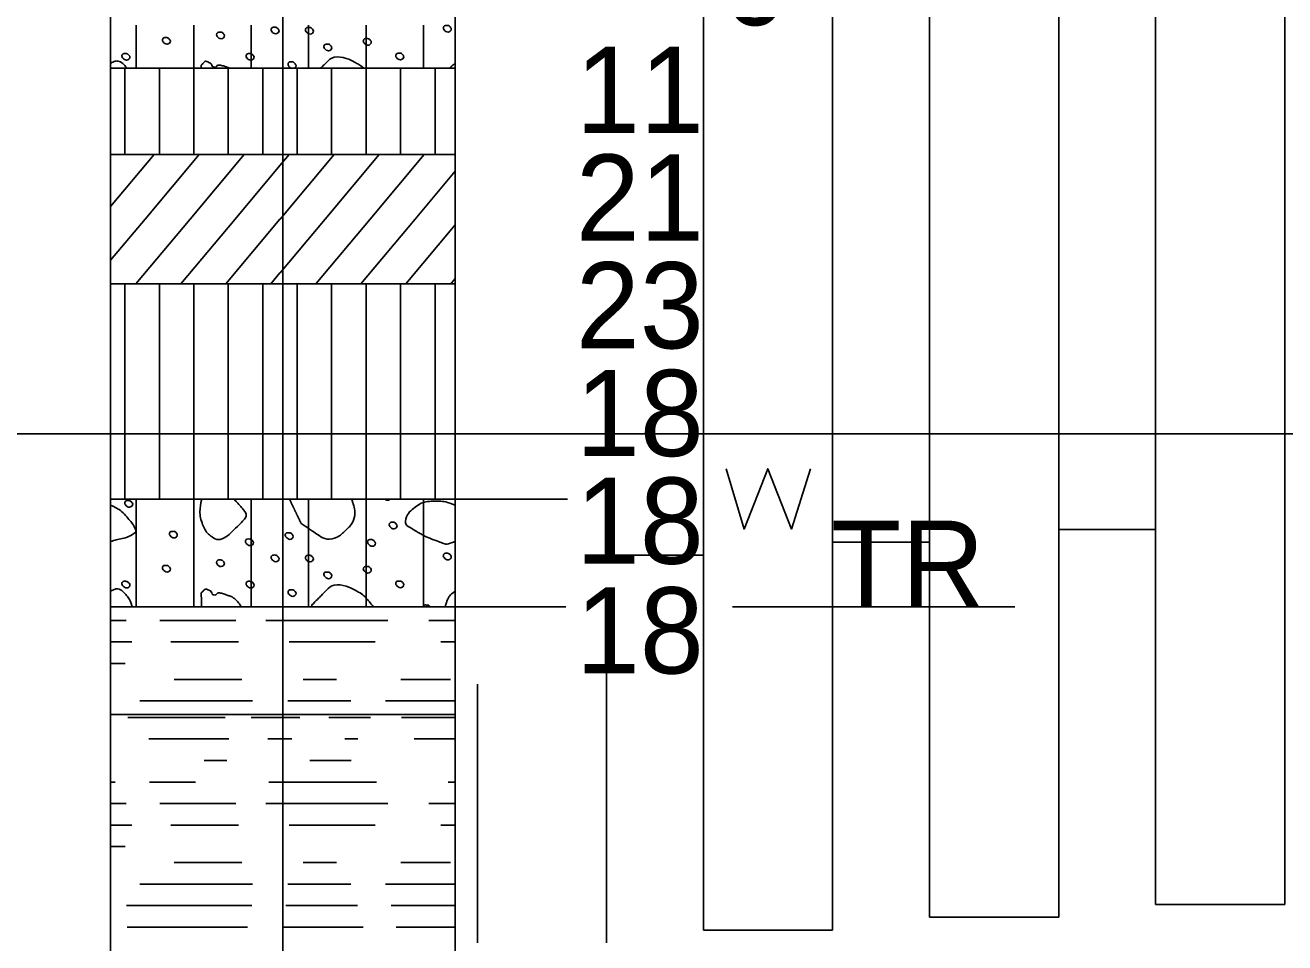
# Model space of a CAD drawing. Extents: x -2280229 to 1306, y -58886 to 440.
# Drawn here: x 316.23 to 345.48, y 70.4 to 91.69 of the extents above; entities that cross this region are included whole.
import ezdxf

# ---------------------------------------------------------------- set-up
doc = ezdxf.new("R2010")
doc.units = 0
for name, color, linetype in [('BR_P_Sub_Deep_Object', 7, 'Continuous'), ('GT_Project_Cells', 7, 'Continuous'), ('GT_Project_Soil_Layers', 7, 'Continuous'), ('SC_Scratch2', 7, 'Continuous'), ('SC_Scratch3', 7, 'Continuous'), ('SH_Minor_Grid_Line', 7, 'Continuous')]:
    doc.layers.add(name, color=color, linetype=linetype)

msp = doc.modelspace()

# ---------------------------------------------------------------- linework, layer by layer
at = {"layer": 'BR_P_Sub_Deep_Object'}
for p, q in [((331.984, 106.857), (331.984, 70.692)), ((334.984, 106.85), (334.984, 70.692)), ((337.234, 106.845), (337.234, 70.988)), ((340.234, 106.839), (340.234, 70.988)), ((342.484, 106.833), (342.484, 71.283)), ((345.484, 106.847), (345.484, 71.283)), ((340.234, 79.988), (342.484, 79.988)), ((334.984, 79.692), (337.234, 79.692)), ((329.734, 79.396), (331.984, 79.396)), ((329.734, 76.788), (329.734, 70.396)), ((326.734, 76.396), (326.734, 70.396)), ((342.484, 71.283), (345.484, 71.283)), ((337.234, 70.988), (340.234, 70.988)), ((331.984, 70.692), (334.984, 70.692))]:
    msp.add_line(p, q, dxfattribs=at)
at = {"layer": 'GT_Project_Cells'}
msp.add_line((328.828, 80.693), (326.219, 80.693), dxfattribs=at)
msp.add_lwpolyline([(332.509, 81.4), (332.927, 80), (333.479, 81.4), (334.03, 80), (334.471, 81.4)], dxfattribs=at)
at = {"layer": 'GT_Project_Soil_Layers'}
for p, q in [((318.815, 90.693), (318.815, 91.692)), ((320.148, 90.693), (320.148, 91.692)), ((321.481, 90.693), (321.481, 91.692)), ((322.817, 90.693), (322.817, 91.692)), ((324.151, 90.693), (324.151, 91.692)), ((325.484, 90.693), (325.484, 91.692)), ((318.551, 89.693), (318.551, 90.693)), ((319.351, 89.693), (319.351, 90.693)), ((320.151, 89.693), (320.151, 90.693)), ((320.951, 89.693), (320.951, 90.693)), ((321.751, 89.693), (321.751, 90.693)), ((322.551, 89.693), (322.551, 90.693)), ((323.351, 89.693), (323.351, 90.693)), ((324.151, 89.693), (324.151, 90.693)), ((324.951, 89.693), (324.951, 90.693)), ((325.751, 89.693), (325.751, 90.693)), ((318.551, 88.693), (318.551, 89.693)), ((319.351, 88.693), (319.351, 89.693)), ((320.151, 88.693), (320.151, 89.693)), ((320.951, 88.693), (320.951, 89.693)), ((321.751, 88.693), (321.751, 89.693)), ((322.551, 88.693), (322.551, 89.693)), ((323.351, 88.693), (323.351, 89.693)), ((324.151, 88.693), (324.151, 89.693)), ((324.951, 88.693), (324.951, 89.693)), ((325.751, 88.693), (325.751, 89.693)), ((318.219, 87.486), (319.232, 88.693)), ((319.018, 87.193), (320.276, 88.693)), ((320.062, 87.193), (321.321, 88.693)), ((322.151, 88.434), (322.368, 88.693)), ((322.154, 87.193), (323.413, 88.693)), ((323.199, 87.193), (324.457, 88.693)), ((324.243, 87.193), (325.502, 88.693)), ((321.107, 87.193), (322.148, 88.434)), ((325.288, 87.193), (326.219, 88.302)), ((318.219, 86.241), (319.018, 87.193)), ((318.803, 85.693), (320.062, 87.193)), ((319.847, 85.693), (321.107, 87.193)), ((320.892, 85.693), (322.151, 87.193)), ((322.154, 85.948), (323.199, 87.193)), ((322.984, 85.693), (324.244, 87.193)), ((324.029, 85.693), (325.288, 87.193)), ((325.073, 85.693), (326.219, 87.058)), ((321.936, 85.693), (322.148, 85.944)), ((326.118, 85.693), (326.219, 85.813)), ((318.551, 83.193), (318.551, 85.693)), ((319.351, 83.193), (319.351, 85.693)), ((320.151, 83.193), (320.151, 85.693)), ((320.951, 83.193), (320.951, 85.693)), ((321.751, 83.193), (321.751, 85.693)), ((322.551, 83.193), (322.551, 85.693)), ((323.351, 83.193), (323.351, 85.693)), ((324.151, 83.193), (324.151, 85.693)), ((324.951, 83.193), (324.951, 85.693)), ((325.751, 83.193), (325.751, 85.693)), ((318.551, 80.693), (318.551, 83.193)), ((319.351, 80.693), (319.351, 83.193)), ((320.151, 80.693), (320.151, 83.193)), ((320.951, 80.693), (320.951, 83.193)), ((321.751, 80.693), (321.751, 83.193)), ((322.551, 80.693), (322.551, 83.193)), ((323.351, 80.693), (323.351, 83.193)), ((324.151, 80.693), (324.151, 83.193)), ((324.951, 80.693), (324.951, 83.193)), ((325.751, 80.693), (325.751, 83.193)), ((318.815, 79.443), (318.815, 80.693)), ((320.148, 79.443), (320.148, 80.693)), ((321.481, 79.443), (321.481, 80.693)), ((322.817, 79.443), (322.817, 80.693)), ((324.151, 79.443), (324.151, 80.693)), ((325.484, 79.443), (325.484, 80.693)), ((318.815, 78.193), (318.815, 79.442)), ((320.148, 78.193), (320.148, 79.442)), ((321.481, 78.193), (321.481, 79.442)), ((322.817, 78.193), (322.817, 79.442)), ((324.151, 78.193), (324.151, 79.442)), ((325.484, 78.193), (325.484, 79.442)), ((318.576, 77.878), (318.219, 77.878)), ((321.128, 77.878), (319.362, 77.878)), ((321.826, 77.878), (322.117, 77.878)), ((324.655, 77.878), (322.117, 77.878)), ((326.219, 77.878), (325.611, 77.878)), ((318.711, 77.378), (318.219, 77.378)), ((321.189, 77.378), (319.618, 77.378)), ((324.36, 77.378), (322.367, 77.378)), ((326.219, 77.378), (325.885, 77.378)), ((318.555, 76.878), (318.219, 76.878)), ((321.264, 76.509), (319.695, 76.509)), ((323.463, 76.509), (322.688, 76.509)), ((326.111, 76.509), (324.958, 76.509)), ((321.515, 76.009), (318.898, 76.009)), ((323.797, 76.009), (322.332, 76.009)), ((326.219, 76.009), (324.601, 76.009)), ((320.881, 75.628), (318.621, 75.628)), ((322.117, 75.628), (321.483, 75.628)), ((322.609, 75.628), (322.117, 75.628)), ((324.254, 75.628), (323.288, 75.628)), ((326.219, 75.628), (324.97, 75.628)), ((320.967, 75.128), (319.108, 75.128)), ((322.117, 75.128), (321.87, 75.128)), ((322.43, 75.128), (322.117, 75.128)), ((323.955, 75.128), (323.655, 75.128)), ((326.219, 75.128), (325.269, 75.128)), ((320.918, 74.628), (320.393, 74.628)), ((323.805, 74.628), (322.844, 74.628)), ((318.32, 74.128), (318.219, 74.128)), ((320.188, 74.128), (319.12, 74.128)), ((321.89, 74.128), (322.117, 74.128)), ((324.395, 74.128), (322.117, 74.128)), ((326.219, 74.128), (326.059, 74.128)), ((318.576, 73.628), (318.219, 73.628)), ((321.128, 73.628), (319.362, 73.628)), ((321.826, 73.628), (322.117, 73.628)), ((324.655, 73.628), (322.117, 73.628)), ((326.219, 73.628), (325.611, 73.628)), ((318.711, 73.128), (318.219, 73.128)), ((321.189, 73.128), (319.618, 73.128)), ((324.36, 73.128), (322.367, 73.128)), ((326.219, 73.128), (325.885, 73.128)), ((318.555, 72.628), (318.219, 72.628)), ((321.264, 72.259), (319.695, 72.259)), ((323.463, 72.259), (322.688, 72.259)), ((326.111, 72.259), (324.958, 72.259)), ((321.515, 71.759), (318.898, 71.759)), ((323.797, 71.759), (322.332, 71.759)), ((326.219, 71.759), (324.601, 71.759)), ((321.498, 71.259), (318.587, 71.259)), ((323.952, 71.259), (322.283, 71.259)), ((326.219, 71.259), (324.736, 71.259)), ((321.394, 70.759), (318.604, 70.759)), ((324.08, 70.759), (322.221, 70.759)), ((326.219, 70.759), (324.85, 70.759))]:
    msp.add_line(p, q, dxfattribs=at)
for points in [[(318.219, 90.693), (326.219, 90.693), (326.219, 92.693), (318.219, 92.693)], [(326.219, 90.693), (318.219, 90.693), (318.219, 88.693), (326.219, 88.693)], [(326.219, 88.693), (318.219, 88.693), (318.219, 85.693), (326.219, 85.693)], [(326.219, 85.693), (318.219, 85.693), (318.219, 80.693), (326.219, 80.693)], [(326.219, 80.693), (318.219, 80.693), (318.219, 78.193), (326.219, 78.193)], [(326.219, 78.193), (318.219, 78.193), (318.219, 75.693), (326.219, 75.693)], [(318.219, 69.693), (326.219, 69.693), (326.219, 75.693), (318.219, 75.693)]]:
    msp.add_lwpolyline(points, close=True, dxfattribs=at)
for points in [[(322.111, 91.6), (322.13, 91.563), (322.106, 91.515), (322.051, 91.492), (322, 91.508), (321.96, 91.547), (321.943, 91.587), (321.975, 91.64), (322.023, 91.647), (322.063, 91.643), (322.111, 91.6)], [(322.908, 91.598), (322.928, 91.558), (322.905, 91.51), (322.85, 91.486), (322.798, 91.505), (322.758, 91.541), (322.741, 91.581), (322.773, 91.636), (322.821, 91.641), (322.861, 91.638), (322.908, 91.598)], [(326.113, 91.641), (326.129, 91.602), (326.106, 91.554), (326.053, 91.532), (326.001, 91.549), (325.961, 91.586), (325.944, 91.626), (325.974, 91.681), (326.024, 91.686), (326.064, 91.684), (326.113, 91.641)], [(319.588, 91.361), (319.605, 91.323), (319.583, 91.275), (319.528, 91.251), (319.477, 91.27), (319.437, 91.306), (319.42, 91.346), (319.45, 91.401), (319.5, 91.406), (319.54, 91.403), (319.588, 91.361)], [(320.845, 91.486), (320.861, 91.45), (320.838, 91.401), (320.785, 91.378), (320.733, 91.395), (320.693, 91.433), (320.675, 91.473), (320.706, 91.526), (320.755, 91.533), (320.795, 91.53), (320.845, 91.486)], [(324.252, 91.339), (324.272, 91.299), (324.249, 91.25), (324.194, 91.227), (324.142, 91.244), (324.102, 91.282), (324.085, 91.322), (324.117, 91.375), (324.165, 91.382), (324.205, 91.379), (324.252, 91.339)], [(318.648, 90.991), (318.667, 90.952), (318.643, 90.904), (318.588, 90.881), (318.537, 90.899), (318.497, 90.936), (318.48, 90.976), (318.512, 91.031), (318.56, 91.036), (318.6, 91.032), (318.648, 90.991)], [(321.532, 90.991), (321.548, 90.952), (321.527, 90.904), (321.472, 90.881), (321.42, 90.899), (321.38, 90.936), (321.363, 90.976), (321.395, 91.031), (321.443, 91.036), (321.483, 91.032), (321.532, 90.991)], [(323.338, 91.207), (323.354, 91.169), (323.333, 91.12), (323.278, 91.097), (323.226, 91.115), (323.186, 91.152), (323.169, 91.192), (323.201, 91.247), (323.249, 91.252), (323.289, 91.249), (323.338, 91.207)], [(325.008, 90.998), (325.025, 90.96), (325.002, 90.911), (324.948, 90.888), (324.897, 90.906), (324.857, 90.943), (324.838, 90.983), (324.87, 91.038), (324.918, 91.043), (324.958, 91.04), (325.008, 90.998)], [(318.712, 80.616), (318.732, 80.576), (318.708, 80.528), (318.653, 80.505), (318.602, 80.523), (318.562, 80.56), (318.545, 80.6), (318.577, 80.655), (318.625, 80.66), (318.665, 80.656), (318.712, 80.616)], [(324.851, 80.115), (324.871, 80.075), (324.848, 80.026), (324.795, 80.003), (324.743, 80.02), (324.703, 80.058), (324.685, 80.098), (324.716, 80.151), (324.766, 80.158), (324.806, 80.155), (324.851, 80.115)], [(319.75, 79.901), (319.767, 79.863), (319.745, 79.815), (319.69, 79.793), (319.638, 79.81), (319.598, 79.846), (319.582, 79.886), (319.613, 79.941), (319.662, 79.946), (319.702, 79.945), (319.75, 79.901)], [(322.441, 79.868), (322.458, 79.831), (322.435, 79.783), (322.381, 79.76), (322.33, 79.776), (322.29, 79.815), (322.271, 79.855), (322.303, 79.908), (322.353, 79.915), (322.393, 79.911), (322.441, 79.868)], [(321.513, 79.726), (321.533, 79.685), (321.51, 79.636), (321.455, 79.615), (321.405, 79.631), (321.363, 79.668), (321.347, 79.708), (321.378, 79.763), (321.427, 79.768), (321.467, 79.766), (321.513, 79.726)], [(324.351, 79.706), (324.37, 79.67), (324.346, 79.621), (324.291, 79.598), (324.24, 79.616), (324.2, 79.653), (324.183, 79.693), (324.215, 79.748), (324.263, 79.753), (324.303, 79.75), (324.351, 79.706)], [(320.845, 79.236), (320.861, 79.2), (320.838, 79.151), (320.785, 79.128), (320.733, 79.145), (320.693, 79.183), (320.675, 79.223), (320.706, 79.276), (320.755, 79.283), (320.795, 79.28), (320.845, 79.236)], [(322.111, 79.35), (322.13, 79.313), (322.106, 79.265), (322.051, 79.242), (322, 79.258), (321.96, 79.297), (321.943, 79.337), (321.975, 79.39), (322.023, 79.397), (322.063, 79.393), (322.111, 79.35)], [(322.908, 79.348), (322.928, 79.308), (322.905, 79.26), (322.85, 79.236), (322.798, 79.255), (322.758, 79.291), (322.741, 79.331), (322.773, 79.386), (322.821, 79.391), (322.861, 79.388), (322.908, 79.348)], [(326.113, 79.391), (326.129, 79.352), (326.106, 79.304), (326.053, 79.282), (326.001, 79.299), (325.961, 79.336), (325.944, 79.376), (325.974, 79.431), (326.024, 79.436), (326.064, 79.434), (326.113, 79.391)], [(319.588, 79.111), (319.605, 79.073), (319.583, 79.025), (319.528, 79.001), (319.477, 79.02), (319.437, 79.056), (319.42, 79.096), (319.45, 79.151), (319.5, 79.156), (319.54, 79.153), (319.588, 79.111)], [(323.338, 78.957), (323.354, 78.919), (323.333, 78.87), (323.278, 78.847), (323.226, 78.865), (323.186, 78.902), (323.169, 78.942), (323.201, 78.997), (323.249, 79.002), (323.289, 78.999), (323.338, 78.957)], [(324.252, 79.089), (324.272, 79.049), (324.249, 79), (324.194, 78.977), (324.142, 78.994), (324.102, 79.032), (324.085, 79.072), (324.117, 79.125), (324.165, 79.132), (324.205, 79.129), (324.252, 79.089)], [(318.648, 78.741), (318.667, 78.702), (318.643, 78.654), (318.588, 78.631), (318.537, 78.649), (318.497, 78.686), (318.48, 78.726), (318.512, 78.781), (318.56, 78.786), (318.6, 78.782), (318.648, 78.741)], [(321.532, 78.741), (321.548, 78.702), (321.527, 78.654), (321.472, 78.631), (321.42, 78.649), (321.38, 78.686), (321.363, 78.726), (321.395, 78.781), (321.443, 78.786), (321.483, 78.782), (321.532, 78.741)], [(325.008, 78.748), (325.025, 78.71), (325.002, 78.661), (324.948, 78.638), (324.897, 78.656), (324.857, 78.693), (324.838, 78.733), (324.87, 78.788), (324.918, 78.793), (324.958, 78.79), (325.008, 78.748)], [(322.506, 78.546), (322.523, 78.509), (322.499, 78.459), (322.446, 78.437), (322.394, 78.454), (322.354, 78.491), (322.338, 78.531), (322.368, 78.586), (322.418, 78.591), (322.458, 78.589), (322.506, 78.546)]]:
    msp.add_spline(points, degree=3, dxfattribs=at)
for points, degree in [([(318.602, 90.693), (318.599, 90.697), (318.595, 90.701), (318.592, 90.706), (318.511, 90.807), (318.382, 90.879), (318.293, 90.844), (318.27, 90.835), (318.244, 90.822), (318.219, 90.806)], 3), ([(320.984, 90.693), (320.951, 90.706), (320.917, 90.717), (320.882, 90.731), (320.836, 90.748), (320.79, 90.758), (320.745, 90.766), (320.702, 90.773), (320.66, 90.711), (320.618, 90.719), (320.574, 90.727), (320.557, 90.805), (320.517, 90.822), (320.481, 90.838), (320.42, 90.864), (320.39, 90.834), (320.367, 90.811), (320.345, 90.788), (320.322, 90.766)], 3), ([(320.322, 90.766), (320.322, 90.741), (320.323, 90.717), (320.324, 90.693)], 2), ([(322.418, 90.693), (322.41, 90.695), (322.402, 90.699), (322.394, 90.704), (322.377, 90.714), (322.366, 90.724), (322.354, 90.741), (322.345, 90.754), (322.338, 90.767), (322.338, 90.781), (322.337, 90.8), (322.347, 90.821), (322.368, 90.836), (322.384, 90.847), (322.401, 90.84), (322.418, 90.841), (322.431, 90.841), (322.448, 90.848), (322.458, 90.839), (322.474, 90.825), (322.49, 90.81), (322.506, 90.796)], 3), ([(322.506, 90.796), (322.512, 90.783), (322.517, 90.771), (322.523, 90.759), (322.53, 90.742), (322.516, 90.726), (322.499, 90.709), (322.492, 90.701), (322.484, 90.696), (322.476, 90.693)], 3), ([(323.095, 90.693), (323.139, 90.736), (323.183, 90.78), (323.226, 90.824), (323.387, 90.984), (323.704, 90.931), (323.906, 90.824), (323.977, 90.787), (324.039, 90.743), (324.097, 90.693)], 3), ([(326.219, 90.804), (326.173, 90.775), (326.128, 90.737), (326.093, 90.693)], 2), ([(318.219, 80.551), (318.246, 80.54), (318.273, 80.527), (318.3, 80.513), (318.458, 80.431), (318.564, 80.318), (318.673, 80.188), (318.743, 80.106), (318.83, 79.936), (318.738, 79.881), (318.604, 79.801), (318.452, 79.771), (318.3, 79.735), (318.273, 79.728), (318.246, 79.719), (318.219, 79.71)], 3), ([(321.088, 80.693), (321.157, 80.614), (321.226, 80.536), (321.295, 80.458), (321.423, 80.313), (321.199, 80.097), (321.037, 79.938), (320.905, 79.809), (320.707, 79.727), (320.583, 79.81), (320.487, 79.875), (320.405, 79.98), (320.357, 80.101), (320.296, 80.256), (320.288, 80.418), (320.308, 80.571), (320.314, 80.612), (320.321, 80.653), (320.331, 80.693)], 3), ([(322.643, 80.126), (322.553, 80.315), (322.462, 80.504), (322.371, 80.693)], 2), ([(323.813, 80.693), (323.83, 80.649), (323.845, 80.605), (323.856, 80.561), (323.905, 80.377), (323.856, 80.14), (323.673, 79.966), (323.489, 79.79), (323.229, 79.735), (323.055, 79.851), (322.917, 79.943), (322.78, 80.035), (322.643, 80.126)], 3), ([(324.706, 80.693), (324.705, 80.692), (324.704, 80.691), (324.703, 80.69), (324.685, 80.672), (324.667, 80.667), (324.648, 80.668), (324.631, 80.669), (324.613, 80.674), (324.596, 80.685), (324.592, 80.687), (324.588, 80.69), (324.585, 80.693)], 3), ([(325.543, 79.816), (325.414, 79.892), (325.284, 79.967), (325.155, 80.043), (325.037, 80.112), (325.1, 80.348), (325.218, 80.448), (325.357, 80.565), (325.502, 80.632), (325.656, 80.643), (325.84, 80.656), (326.034, 80.631), (326.219, 80.553)], 3), ([(326.219, 79.709), (326.121, 79.675), (326.023, 79.635), (325.931, 79.67), (325.802, 79.719), (325.672, 79.767), (325.543, 79.816)], 3), ([(322.886, 78.234), (323, 78.347), (323.113, 78.461), (323.226, 78.574), (323.387, 78.734), (323.704, 78.681), (323.906, 78.574), (324.047, 78.5), (324.155, 78.4), (324.263, 78.266), (324.282, 78.242), (324.301, 78.218), (324.319, 78.193)], 3), ([(318.716, 78.193), (318.695, 78.281), (318.661, 78.369), (318.592, 78.456), (318.511, 78.557), (318.382, 78.629), (318.293, 78.594), (318.27, 78.585), (318.244, 78.572), (318.219, 78.556)], 3), ([(321.246, 78.193), (321.218, 78.255), (321.173, 78.316), (321.112, 78.367), (321.037, 78.43), (320.964, 78.45), (320.882, 78.481), (320.836, 78.498), (320.79, 78.508), (320.745, 78.516), (320.702, 78.523), (320.66, 78.461), (320.618, 78.469), (320.574, 78.477), (320.557, 78.555), (320.517, 78.572), (320.481, 78.588), (320.42, 78.614), (320.39, 78.584), (320.367, 78.561), (320.345, 78.538), (320.322, 78.516)], 3), ([(320.322, 78.516), (320.325, 78.408), (320.328, 78.3), (320.331, 78.193)], 2), ([(326.219, 78.554), (326.148, 78.509), (326.078, 78.441), (326.045, 78.364), (326.028, 78.326), (326.015, 78.287), (326, 78.249)], 3), ([(322.897, 78.193), (322.893, 78.206), (322.89, 78.22), (322.886, 78.234)], 2), ([(325.481, 78.193), (325.485, 78.206), (325.495, 78.219), (325.51, 78.229), (325.526, 78.241), (325.543, 78.234), (325.56, 78.234), (325.573, 78.234), (325.59, 78.241), (325.6, 78.232), (325.615, 78.219), (325.629, 78.206), (325.644, 78.193)], 3), ([(326, 78.249), (325.995, 78.23), (325.991, 78.211), (325.987, 78.193)], 2)]:
    msp.add_open_spline(points, degree=degree, dxfattribs=at)
at = {"layer": 'SC_Scratch2'}
for p, q in [((318.219, 106.693), (318.219, 60.693)), ((322.219, 106.693), (322.219, 60.693)), ((326.219, 106.693), (326.219, 60.693)), ((318.219, 90.693), (326.219, 90.693)), ((318.219, 88.693), (326.219, 88.693)), ((318.219, 85.693), (326.219, 85.693)), ((318.219, 80.693), (326.219, 80.693)), ((318.219, 78.193), (326.219, 78.193)), ((318.219, 75.693), (326.219, 75.693))]:
    msp.add_line(p, q, dxfattribs=at)
at = {"layer": 'SC_Scratch3'}
for p, q in [((326.219, 78.193), (328.786, 78.193)), ((332.657, 78.193), (339.219, 78.193))]:
    msp.add_line(p, q, dxfattribs=at)
at = {"layer": 'SH_Minor_Grid_Line'}
msp.add_line((45.429, 82.208), (603.007, 82.208), dxfattribs=at)

# ---------------------------------------------------------------- texts
at = {"layer": 'SC_Scratch2'}
for s, p in [('6', (332.406, 91.693)), ('11', (329.019, 89.193)), ('21', (329.019, 86.693)), ('23', (329.019, 84.193)), ('18', (329.019, 81.693)), ('18', (329.019, 79.193)), ('TR', (334.949, 78.193)), ('18', (329.019, 76.647))]:
    msp.add_text(s, height=2, dxfattribs=at).set_placement(p)

doc.saveas('drawing.dxf')
